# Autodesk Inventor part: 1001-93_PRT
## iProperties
Created: 2011-02
Part Number: 1001-93_PRT
Document SubType Name: Modeling
Designer: Administrator
Density: 1.06 g/cm^3
Material: ABS Plastic
Mass: 5.42818 g
Surface Area: 60.9833 cm^2
Volume: 5.12093 cm^3
Author: Administrator
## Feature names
1. Base1
